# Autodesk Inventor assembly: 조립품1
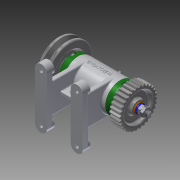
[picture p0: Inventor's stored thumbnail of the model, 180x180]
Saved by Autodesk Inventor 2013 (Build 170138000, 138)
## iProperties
Created: 2015-11
Part Number: 조립품1
Document SubType Name: Assembly
Designer: default
Author: default
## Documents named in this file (16)
- C:\Documents and Settings\default\바탕 화면\451110V1038\조립품1.iam
- C:\Documents and Settings\default\바탕 화면\451110V1038\부품1.ipt
- C:\Documents and Settings\default\바탕 화면\451110v1038 (2)\니플 M 6 x 0.75.ipt
- C:\Documents and Settings\default\바탕 화면\451110v1038 (2)\베어링 15 x 32 x 9.ipt
- C:\Documents and Settings\default\바탕 화면\451110v1038 (2)\볼트 M4 x 12.ipt
- C:\Documents and Settings\default\바탕 화면\451110v1038 (2)\볼트 M 6 x 8.ipt
- C:\Documents and Settings\default\바탕 화면\451110v1038 (2)\스퍼기어.ipt
- C:\Documents and Settings\default\바탕 화면\451110v1038 (2)\스프링와셔 8.ipt
- C:\Documents and Settings\default\바탕 화면\451110v1038 (2)\오일 실 15 25 7.ipt
- C:\Documents and Settings\default\바탕 화면\451110v1038 (2)\와셔 6x11.5.ipt
- C:\Documents and Settings\default\바탕 화면\451110v1038 (2)\와셔 8x17.ipt
- C:\Documents and Settings\default\바탕 화면\451110v1038 (2)\축.ipt
- C:\Documents and Settings\default\바탕 화면\451110v1038 (2)\커버.ipt
- C:\Documents and Settings\default\바탕 화면\451110v1038 (2)\키 3 x 3 x 12.ipt
- C:\Documents and Settings\default\바탕 화면\451110v1038 (2)\V벨트풀리.ipt
- C:\Documents and Settings\default\바탕 화면\451110v1038 (2)\너트 M 8.ipt
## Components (11 placed, 3 different names)
1. KS B 2023 6002 - 15 x 32 x 9:1
2. KS B 2023 6002 - 15 x 32 x 9:2
3. V벨트풀리:3
4. ISO 4762 M4 x 12:1
5. ISO 4762 M4 x 12:3
6. ISO 4762 M4 x 12:4
7. ISO 4762 M4 x 12:5
8. ISO 4762 M4 x 12:2
9. ISO 4762 M4 x 12:6
10. ISO 4762 M4 x 12:7
11. ISO 4762 M4 x 12:8
